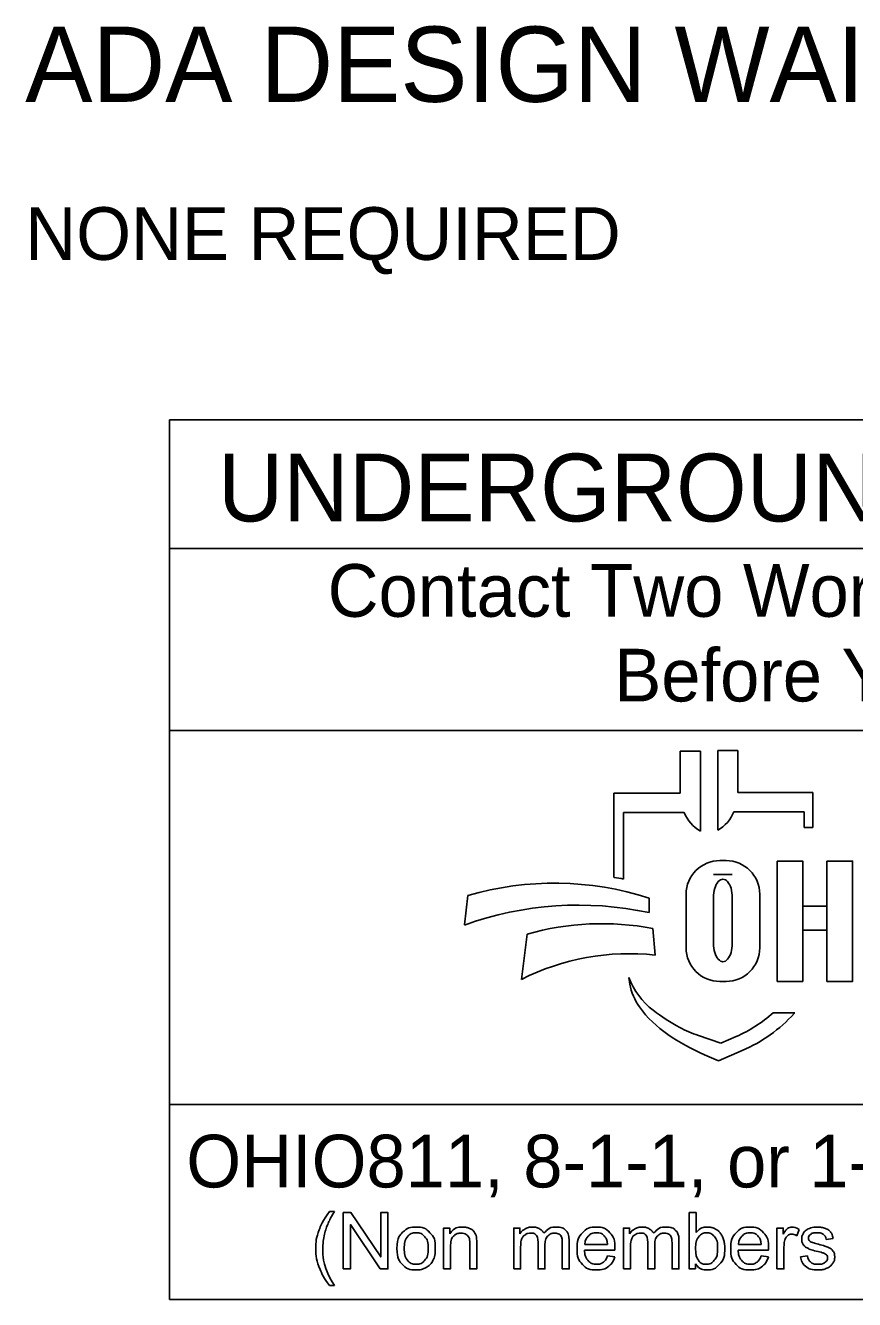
# Model space of a CAD drawing. Extents: x 21.4 to 65.3, y 4 to 26.
# Drawn here: x 23.442 to 25.644, y 6.097 to 9.483 of the extents above; entities that cross this region are included whole.
import ezdxf

# ---------------------------------------------------------------- set-up
doc = ezdxf.new("R2010")
doc.units = 0
doc.layers.add('SH_Data', color=7, linetype='Continuous')
doc.layers.add('SH_Text', color=7, linetype='Continuous')

msp = doc.modelspace()

# ---------------------------------------------------------------- linework, layer by layer
at = {"layer": 'SH_Data'}
for p, q in [((23.8248, 6.0969), (23.8248, 8.4344)), ((28.0748, 8.4344), (23.8248, 8.4344)), ((23.8248, 8.0929), (28.0748, 8.0929)), ((23.8248, 7.6095), (28.0748, 7.6095)), ((28.0748, 6.6148), (23.8248, 6.6148)), ((28.0748, 6.0969), (23.8248, 6.0969))]:
    msp.add_line(p, q, dxfattribs=at)
at = {"layer": 'SH_Text'}
for p, q in [((25.1809, 7.4425), (25.1809, 7.5539)), ((25.1809, 7.5539), (25.2345, 7.5539)), ((25.2345, 7.5539), (25.2345, 7.3419)), ((25.2802, 7.3442), (25.2802, 7.5563)), ((25.2802, 7.5563), (25.3338, 7.5563)), ((25.3338, 7.5563), (25.3338, 7.4448)), ((25.0049, 7.2186), (25.0049, 7.4425)), ((25.0049, 7.4425), (25.1809, 7.4425)), ((25.3338, 7.4448), (25.5331, 7.4448)), ((25.5331, 7.4448), (25.5331, 7.351)), ((25.0302, 7.391), (25.0302, 7.2142)), ((25.1913, 7.391), (25.0302, 7.391)), ((25.5098, 7.3933), (25.3234, 7.3933)), ((25.5098, 7.351), (25.5098, 7.3933)), ((25.5331, 7.351), (25.5098, 7.351)), ((25.2859, 7.2633), (25.3024, 7.2633)), ((25.3191, 7.2263), (25.2693, 7.2263)), ((24.6076, 7.0923), (24.6169, 7.1704)), ((25.0982, 7.1639), (25.0982, 7.1251)), ((25.1964, 7.0318), (25.1964, 7.1738)), ((25.2693, 7.0432), (25.2693, 7.1655)), ((25.3191, 7.1655), (25.3191, 7.0432)), ((25.3919, 7.1738), (25.3919, 7.0318)), ((25.1082, 7.0833), (25.1144, 7.0123)), ((24.7594, 6.9477), (24.7741, 7.0679)), ((25.0471, 6.9348), (25.044, 6.9528)), ((25.3024, 6.9423), (25.2859, 6.9423)), ((25.4274, 6.859), (25.4848, 6.859)), ((25.2289, 6.7986), (25.2883, 6.7781)), ((25.2883, 6.7781), (25.3294, 6.7959)), ((25.2823, 6.7311), (25.245, 6.7475)), ((25.3456, 6.7585), (25.2823, 6.7311))]:
    msp.add_line(p, q, dxfattribs=at)
for points in [[(25.4383, 7.2622), (25.5063, 7.2622), (25.5063, 6.9422), (25.4383, 6.9422)], [(25.5704, 7.2622), (25.6384, 7.2622), (25.6384, 6.9422), (25.5704, 6.9422)], [(25.5063, 7.1423), (25.5704, 7.1423), (25.5704, 7.0783), (25.5063, 7.0783)]]:
    msp.add_lwpolyline(points, close=True, dxfattribs=at)
for points in [[(24.2495, 6.3307), (24.2626, 6.3307)], [(24.2862, 6.1781), (24.2862, 6.3282), (24.3065, 6.3282), (24.3855, 6.2103), (24.3855, 6.3282), (24.4045, 6.3282), (24.4045, 6.1781), (24.3842, 6.1781), (24.3052, 6.296), (24.3052, 6.1781), (24.2862, 6.1781)], [(25.2217, 6.1781), (25.2046, 6.1781), (25.2046, 6.3282), (25.223, 6.3282), (25.223, 6.2747)], [(24.5522, 6.1781), (24.5522, 6.2869), (24.5688, 6.2869), (24.5688, 6.2714)], [(24.7386, 6.1781), (24.7386, 6.2869), (24.755, 6.2869), (24.755, 6.2716)], [(25.0299, 6.1781), (25.0299, 6.2869), (25.0464, 6.2869), (25.0464, 6.2716)], [(25.4377, 6.1781), (25.4377, 6.2869), (25.4543, 6.2869), (25.4543, 6.2704)], [(25.4968, 6.2834), (25.4903, 6.2664)], [(24.5706, 6.2375), (24.5706, 6.1781), (24.5522, 6.1781)], [(24.6405, 6.245), (24.6405, 6.1781), (24.6221, 6.1781), (24.6221, 6.2442)], [(24.757, 6.2345), (24.757, 6.1781), (24.7386, 6.1781)], [(24.8217, 6.2412), (24.8217, 6.1781), (24.8032, 6.1781), (24.8032, 6.2487)], [(24.8861, 6.2527), (24.8861, 6.1781), (24.8677, 6.1781), (24.8677, 6.2466)], [(24.9272, 6.2429), (24.988, 6.2429)], [(25.0484, 6.2345), (25.0484, 6.1781), (25.0299, 6.1781)], [(25.113, 6.2412), (25.113, 6.1781), (25.0946, 6.1781), (25.0946, 6.2487)], [(25.1775, 6.2527), (25.1775, 6.1781), (25.159, 6.1781), (25.159, 6.2466)], [(25.3352, 6.2429), (25.396, 6.2429)], [(25.4562, 6.2351), (25.4562, 6.1781), (25.4377, 6.1781)], [(25.5867, 6.2588), (25.5686, 6.2564)], [(25.0073, 6.2277), (24.9262, 6.2277)], [(24.9878, 6.2132), (25.0068, 6.2108)], [(25.4153, 6.2277), (25.3342, 6.2277)], [(25.3957, 6.2132), (25.4148, 6.2108)], [(25.5003, 6.2106), (25.5185, 6.2134)], [(25.2217, 6.1917), (25.2217, 6.1781)], [(24.2626, 6.1339), (24.2495, 6.1339)]]:
    msp.add_lwpolyline(points, dxfattribs=at)
for centre, radius, start, end in [((25.2826, 7.4278), 0.0985, 201.9296, 240.7469), ((25.2321, 7.4301), 0.0985, 299.2531, 338.0704), ((25.2859, 7.1738), 0.0895, 90, 180), ((25.3024, 7.1738), 0.0895, 0, 90), ((24.8768, 6.4096), 0.8191, 79.2074, 81.0007), ((24.847, 6.3843), 0.8191, 72.1402, 106.3144), ((24.9101, 6.2532), 0.8919, 77.8238, 109.8274), ((24.974, 6.3635), 0.7322, 79.44, 105.8467), ((25.046, 6.3803), 0.6357, 83.8248, 116.8021), ((25.2859, 7.0318), 0.0895, 180, 270), ((25.3024, 7.0318), 0.0895, 270, 0), ((25.2314, 7.0249), 0.2008, 201.0457, 232.5314), ((25.1884, 6.9589), 0.1433, 189.6817, 216.0884), ((25.322, 7.0564), 0.3088, 216.0884, 235.7167), ((25.4239, 7.2761), 0.5173, 232.5314, 241.794), ((25.186, 7.1264), 0.3602, 293.4582, 312.0712), ((25.186, 7.1264), 0.401, 293.4582, 317.8286), ((25.3388, 7.1173), 0.3371, 241.794, 250.9821), ((25.4885, 7.3006), 0.6044, 235.7167, 246.2325)]:
    msp.add_arc(centre, radius, start, end, dxfattribs=at)
for centre, start_param, end_param in [((25.2942, 7.1655), 4.712389, 7.853982), ((25.2942, 7.0432), 1.570796, 4.712389)]:
    msp.add_ellipse(centre, major_axis=(0, 0.0484), ratio=0.514403, start_param=start_param, end_param=end_param, dxfattribs=at)
for points in [[(24.2495, 6.1339), (24.2342, 6.1532), (24.2236, 6.179), (24.2131, 6.2048), (24.2131, 6.2324), (24.2131, 6.2568), (24.221, 6.2791), (24.2302, 6.305), (24.2495, 6.3307)], [(24.2626, 6.3307), (24.2503, 6.3094), (24.2463, 6.3003), (24.24, 6.2862), (24.2365, 6.2708), (24.2321, 6.2517), (24.2321, 6.2323), (24.2321, 6.1831), (24.2626, 6.1339)], [(24.4287, 6.2325), (24.4287, 6.2627), (24.4455, 6.2772), (24.4595, 6.2893), (24.4797, 6.2893), (24.5021, 6.2893), (24.5163, 6.2746), (24.5305, 6.2599), (24.5305, 6.234), (24.5305, 6.213), (24.5242, 6.201), (24.5179, 6.189), (24.5059, 6.1823), (24.4939, 6.1757), (24.4797, 6.1757), (24.4568, 6.1757), (24.4428, 6.1903), (24.4287, 6.205), (24.4287, 6.2325)], [(24.4477, 6.2325), (24.4477, 6.2116), (24.4568, 6.2012), (24.4659, 6.1908), (24.4797, 6.1908), (24.4933, 6.1908), (24.5024, 6.2012), (24.5115, 6.2117), (24.5115, 6.2331), (24.5115, 6.2533), (24.5024, 6.2637), (24.4932, 6.2741), (24.4797, 6.2741), (24.4659, 6.2741), (24.4568, 6.2637), (24.4477, 6.2534), (24.4477, 6.2325)], [(24.5688, 6.2714), (24.5807, 6.2893), (24.6034, 6.2893), (24.6132, 6.2893), (24.6214, 6.2858), (24.6297, 6.2822), (24.6338, 6.2765), (24.6379, 6.2708), (24.6395, 6.2629), (24.6405, 6.2578), (24.6405, 6.245)], [(24.6221, 6.2442), (24.6221, 6.2555), (24.6199, 6.2611), (24.6178, 6.2666), (24.6123, 6.27), (24.6068, 6.2733), (24.5995, 6.2733), (24.5877, 6.2733), (24.5791, 6.2658), (24.5706, 6.2583), (24.5706, 6.2375)], [(24.755, 6.2716), (24.7602, 6.2796), (24.7687, 6.2844), (24.7772, 6.2893), (24.788, 6.2893), (24.8001, 6.2893), (24.8079, 6.2843), (24.8156, 6.2793), (24.8188, 6.2702), (24.8317, 6.2893), (24.8524, 6.2893), (24.8686, 6.2893), (24.8774, 6.2804), (24.8861, 6.2714), (24.8861, 6.2527)], [(24.8032, 6.2487), (24.8032, 6.261), (24.7987, 6.2672), (24.7942, 6.2733), (24.784, 6.2733), (24.7762, 6.2733), (24.7696, 6.2692), (24.7629, 6.2651), (24.76, 6.2572), (24.757, 6.2493), (24.757, 6.2345)], [(24.8677, 6.2466), (24.8677, 6.2576), (24.8659, 6.2625), (24.8641, 6.2674), (24.8594, 6.2703), (24.8546, 6.2733), (24.8483, 6.2733), (24.8368, 6.2733), (24.8292, 6.2657), (24.8217, 6.258), (24.8217, 6.2412)], [(25.0068, 6.2108), (25.0023, 6.1941), (24.9901, 6.1849), (24.9779, 6.1757), (24.959, 6.1757), (24.9351, 6.1757), (24.9211, 6.1904), (24.9072, 6.2051), (24.9072, 6.2316), (24.9072, 6.259), (24.9213, 6.2742), (24.9354, 6.2893), (24.958, 6.2893), (24.9798, 6.2893), (24.9936, 6.2745), (25.0074, 6.2596), (25.0074, 6.2327), (25.0074, 6.231), (25.0073, 6.2277)], [(24.988, 6.2429), (24.9867, 6.2566), (24.981, 6.2635), (24.9722, 6.2742), (24.9581, 6.2742), (24.9454, 6.2742), (24.9368, 6.2657), (24.9281, 6.2571), (24.9272, 6.2429)], [(25.0464, 6.2716), (25.0515, 6.2796), (25.0601, 6.2844), (25.0686, 6.2893), (25.0794, 6.2893), (25.0915, 6.2893), (25.0992, 6.2843), (25.107, 6.2793), (25.1102, 6.2702), (25.1231, 6.2893), (25.1438, 6.2893), (25.16, 6.2893), (25.1687, 6.2804), (25.1775, 6.2714), (25.1775, 6.2527)], [(25.0946, 6.2487), (25.0946, 6.261), (25.0901, 6.2672), (25.0856, 6.2733), (25.0753, 6.2733), (25.0675, 6.2733), (25.0609, 6.2692), (25.0543, 6.2651), (25.0513, 6.2572), (25.0484, 6.2493), (25.0484, 6.2345)], [(25.159, 6.2466), (25.159, 6.2576), (25.1572, 6.2625), (25.1554, 6.2674), (25.1507, 6.2703), (25.146, 6.2733), (25.1397, 6.2733), (25.1282, 6.2733), (25.1206, 6.2657), (25.113, 6.258), (25.113, 6.2412)], [(25.2214, 6.2333), (25.2214, 6.2137), (25.2267, 6.205), (25.2354, 6.1908), (25.2503, 6.1908), (25.2623, 6.1908), (25.2711, 6.2013), (25.2799, 6.2118), (25.2799, 6.2326), (25.2799, 6.2539), (25.2715, 6.2641), (25.263, 6.2742), (25.2511, 6.2742), (25.239, 6.2742), (25.2302, 6.2637), (25.2214, 6.2532), (25.2214, 6.2333)], [(25.223, 6.2747), (25.2347, 6.2893), (25.2528, 6.2893), (25.2629, 6.2893), (25.2718, 6.2853), (25.2808, 6.2812), (25.2866, 6.2739), (25.2924, 6.2666), (25.2956, 6.2562), (25.2989, 6.2459), (25.2989, 6.2341), (25.2989, 6.2062), (25.2851, 6.1909), (25.2712, 6.1757), (25.2519, 6.1757), (25.2326, 6.1757), (25.2217, 6.1917)], [(25.4148, 6.2108), (25.4103, 6.1941), (25.3981, 6.1849), (25.3859, 6.1757), (25.367, 6.1757), (25.3431, 6.1757), (25.3291, 6.1904), (25.3152, 6.2051), (25.3152, 6.2316), (25.3152, 6.259), (25.3293, 6.2742), (25.3434, 6.2893), (25.3659, 6.2893), (25.3878, 6.2893), (25.4016, 6.2745), (25.4154, 6.2596), (25.4154, 6.2327), (25.4154, 6.231), (25.4153, 6.2277)], [(25.396, 6.2429), (25.3947, 6.2566), (25.389, 6.2635), (25.3802, 6.2742), (25.3661, 6.2742), (25.3534, 6.2742), (25.3448, 6.2657), (25.3361, 6.2571), (25.3352, 6.2429)], [(25.4543, 6.2704), (25.4607, 6.282), (25.466, 6.2856), (25.4714, 6.2893), (25.4779, 6.2893), (25.4872, 6.2893), (25.4968, 6.2834)], [(25.4903, 6.2664), (25.4836, 6.2703), (25.4769, 6.2703), (25.4709, 6.2703), (25.4661, 6.2667), (25.4613, 6.263), (25.4592, 6.2566), (25.4562, 6.2467), (25.4562, 6.2351)], [(25.5686, 6.2564), (25.5674, 6.2648), (25.5615, 6.2695), (25.5556, 6.2742), (25.5449, 6.2742), (25.5321, 6.2742), (25.5267, 6.27), (25.5213, 6.2658), (25.5213, 6.2602), (25.5213, 6.2566), (25.5235, 6.2537), (25.5258, 6.2507), (25.5306, 6.2488), (25.5334, 6.2477), (25.5469, 6.244), (25.5665, 6.2388), (25.5743, 6.2355), (25.582, 6.2322), (25.5864, 6.2258), (25.5909, 6.2195), (25.5909, 6.2101), (25.5909, 6.2009), (25.5855, 6.1927), (25.5801, 6.1846), (25.5699, 6.1801), (25.5598, 6.1757), (25.5469, 6.1757), (25.5257, 6.1757), (25.5145, 6.1845), (25.5034, 6.1933), (25.5003, 6.2106)], [(25.5185, 6.2134), (25.5201, 6.2025), (25.5271, 6.1966), (25.5341, 6.1908), (25.5468, 6.1908), (25.5595, 6.1908), (25.5657, 6.196), (25.5719, 6.2011), (25.5719, 6.2081), (25.5719, 6.2144), (25.5664, 6.218), (25.5626, 6.2204), (25.5475, 6.2242), (25.5272, 6.2293), (25.5194, 6.2331), (25.5115, 6.2368), (25.5075, 6.2434), (25.5034, 6.25), (25.5034, 6.258), (25.5034, 6.2653), (25.5068, 6.2715), (25.5101, 6.2776), (25.5158, 6.2817), (25.5201, 6.2849), (25.5276, 6.2871), (25.535, 6.2893), (25.5435, 6.2893), (25.5564, 6.2893), (25.5661, 6.2856), (25.5758, 6.2819), (25.5804, 6.2756), (25.585, 6.2693), (25.5867, 6.2588)], [(24.9262, 6.2277), (24.9272, 6.2098), (24.9363, 6.2003), (24.9454, 6.1908), (24.9591, 6.1908), (24.9692, 6.1908), (24.9764, 6.1961), (24.9836, 6.2015), (24.9878, 6.2132)], [(25.3342, 6.2277), (25.3352, 6.2098), (25.3443, 6.2003), (25.3534, 6.1908), (25.3671, 6.1908), (25.3772, 6.1908), (25.3844, 6.1961), (25.3915, 6.2015), (25.3957, 6.2132)]]:
    msp.add_open_spline(points, degree=3, dxfattribs=at)

# ---------------------------------------------------------------- texts
for s, height, p in [('ADA DESIGN WAIVERS', 0.2, (23.4417, 9.2798)), ('NONE REQUIRED', 0.14, (23.4417, 8.8598)), ('UNDERGROUND UTILITIES', 0.18, (23.953, 8.1648)), ('Contact Two Working Days', 0.14, (24.2445, 7.9113)), ('Before You Dig', 0.14, (25.0057, 7.6863)), ('OHIO811, 8-1-1, or 1-800-362-2764', 0.14, (23.8693, 6.3948))]:
    msp.add_text(s, height=height, dxfattribs=at).set_placement(p)

doc.saveas('drawing.dxf')
